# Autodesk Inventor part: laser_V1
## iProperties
Shininess: 64.0
Length Units: 11269
Angle Units: 11279
Time Units: 11290
Mass Units: 11283
Length Display Precision: 3
Angle Display Precision: 2
Compacted: True
Part Number: laser_V1
Document SubType Name: Modeling
Created: 2004-08
Designer: John Blackburn
Manufacturer: Standard
Standards Organization: Custom
Material: Aluminum-6061
Density: 0.0
Volumn: 0.0
Area: 0.0
PropertySet Name: Model Information
Control State: 0
Master: False
Checked Out: False
Author: John Blackburn
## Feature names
1. Extrusion1
2. Extrusion2
3. Hole1
4. Extrusion5
